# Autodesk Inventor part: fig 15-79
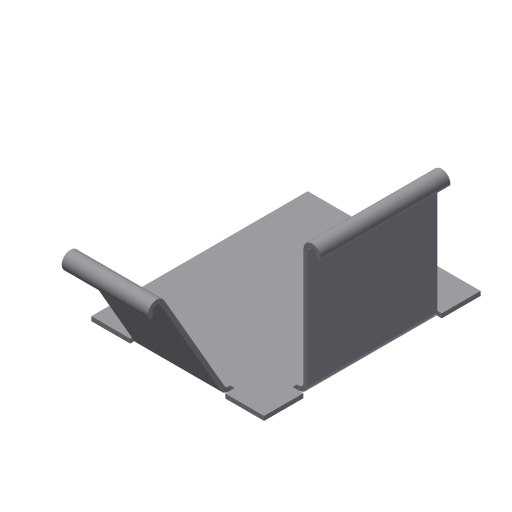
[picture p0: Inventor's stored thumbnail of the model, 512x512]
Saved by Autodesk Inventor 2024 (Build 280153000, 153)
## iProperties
Shininess: 77.0
Angle Display Precision: 2
Document Length Units: 11269
Document Angle Units: 11279
Document Time Units: 11290
Document Mass Units: 11283
Document Length Units Precision: 3
Document Angle Units Precision: 2
Compacted: True
Created: 2002-04
Part Number: fig 15-79
Document SubType Name: Sheet Metal
Density: 1 g/cm^3
Sheet Metal Rule: Default
Material: Generic
Appearance: Default
Density: 0.0
Volumn: 0.0
Area: 0.0
PropertySet Name: Model Information
Control State: 0
Master: False
Checked Out: False
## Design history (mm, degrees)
node "Face1"
  sketch "Sketch1"
    geometry: L1 (-17.882, 11.882)-(2.118, 11.882); L2 (2.118, 11.882)-(2.118, -13.176); L3 (2.118, -13.176)-(-17.882, -13.176); L4 (-17.882, -13.176)-(-17.882, 11.882)
    constraints: 8 end point, 2 parallel, 1 horizontal, 1 perpendicular
    dimensions: "d17" = 20 distance of L2.end L3.end
node "Flange2"
node "Flange3"
feature "Hem8" dims "d82" = 0.5 (= BendReliefWidth), "d83" = 0.25 (= BendReliefDepth), "d84" = 1 (= MinimumRemnant), "d85" = 0.5 (= BendRadius), "d102" = 190 deg, "d103" = 0.5 (= BendRadius), "d104" = 0.5 (= d103), "d108" = 0.5 (= Thickness), "SeamGap" = 0.01
feature "Hem9" dims "d89" = 0.5 (= BendReliefWidth), "d90" = 0.25 (= BendReliefDepth), "d91" = 1 (= MinimumRemnant), "d92" = 0.5 (= BendRadius), "d105" = 190 deg, "d106" = 0.5 (= BendRadius), "d107" = 0.5 (= d106), "d108" = 0.5 (= Thickness), "SeamGap" = 0.01
body "Solid1"
face "Plate1" dims "d108" = 0.5 (= Thickness)
sketch "Sketch3"
  geometry: L1 (5, 0)-(20, 0); L2 (20, 0)-(20, 15); L3 (20, 15)-(5, 15); L4 (5, 15)-(5, 0)
  constraints: 8 end point
face "Plate3" dims "d6" = 15, "d7" = 90 deg, "d8" = 0.5 (= BendRadius), "d18" = 5, "d19" = 15, "d108" = 0.5 (= Thickness), "MinimumRemnant" = 1 (= 2 x Thickness), "BendReliefWidth" = 0.5 (= Thickness)
bend "Bend2" dims "d6" = 15, "d7" = 90 deg, "d8" = 0.5 (= BendRadius), "d56" = 0.5 (= BendReliefWidth), "d57" = 0.25 (= BendReliefDepth), "d58" = 1 (= MinimumRemnant), "d108" = 0.5 (= Thickness), "SeamGap" = 0.01, "MinimumRemnant" = 1 (= 2 x Thickness), "BendReliefWidth" = 0.5 (= Thickness), "TransitionRadius" = 0.5 (= BendRadius)
sketch "Sketch6"
  geometry: L1 (15, 0)-(5, 0); L2 (5, 0)-(5, 15); L3 (5, 15)-(15, 15); L4 (15, 15)-(15, 0)
  constraints: 8 end point
face "Plate4" dims "d20" = 5, "d21" = 10, "d23" = 15, "d24" = 60 deg, "d25" = 0.5 (= BendRadius), "d108" = 0.5 (= Thickness), "MinimumRemnant" = 1 (= 2 x Thickness), "BendReliefWidth" = 0.5 (= Thickness)
bend "Bend3" dims "d22" = 0.5 (= BendRadius), "d23" = 15, "d24" = 60 deg, "d25" = 0.5 (= BendRadius), "d59" = 0.5 (= BendReliefWidth), "d60" = 0.25 (= BendReliefDepth), "d61" = 1 (= MinimumRemnant), "d108" = 0.5 (= Thickness), "SeamGap" = 0.01, "MinimumRemnant" = 1 (= 2 x Thickness), "BendReliefWidth" = 0.5 (= Thickness)
sketch "Sketch12"
  geometry: L1 (0.433, 0.25)-(0, 0); L2 (-0.816, -0.571)-(-1.199, -0.893); A1 r 0.5 centre (-0.433, -0.25) between (0, 0) and (-0.816, -0.571); A2 r 1 centre (-0.433, -0.25) between (0.433, 0.25) and (-1.199, -0.893); 2 further points
  constraints: 4 end point, 4 point on circle
sketch "Sketch13"
  geometry: L1 (0.5, 0)-(0, 0); L2 (-0.992, -0.087)-(-1.485, -0.174); A1 r 0.5 centre (-0.5, 0) between (0, 0) and (-0.992, -0.087); A2 r 1 centre (-0.5, 0) between (0.5, 0) and (-1.485, -0.174); 2 further points
  constraints: 4 end point, 4 point on circle
other parameters: "Thickness" = 0.5, "BendRadius" = 0.5 (= Thickness), "BendReliefDepth" = 0.25 (= 0.5 x Thickness), "CornerReliefSize" = 2 (= 4 x Thickness), "d0" = 0.5 (= BendRadius), "d5" = 0.5 (= BendRadius), "d26" = 0.5 (= BendRadius), "d30" = 0.5 (= BendRadius), "JacobiRadiusSize" = 0.5 (= Thickness), "GapSize" = 0.5 (= Thickness)
